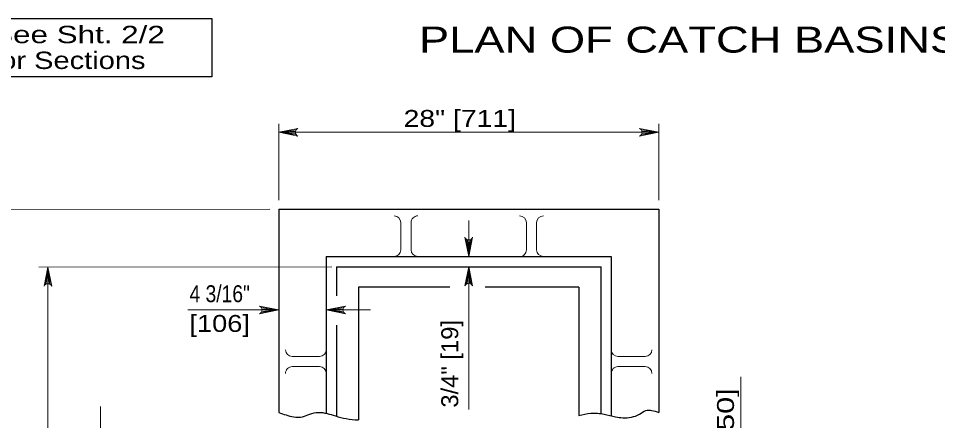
# Model space of a CAD drawing. Extents: x 1083.1 to 1117.1, y 719.4 to 763.4.
# Drawn here: x 1087.41 to 1095.88, y 747.79 to 751.5 of the extents above; entities that cross this region are included whole.
import ezdxf
from ezdxf.enums import TextEntityAlignment as Align

# ---------------------------------------------------------------- set-up
doc = ezdxf.new("R2010")
doc.units = 0
doc.header["$LTSCALE"] = 0.062
doc.layers.add('1', color=7, linetype='Continuous', lineweight=13)

msp = doc.modelspace()

# ---------------------------------------------------------------- linework, layer by layer
at = {"layer": '1'}
for p, q in [((1089.807, 749.82683), (1089.807, 750.53)), ((1089.96733, 750.47425), (1089.807, 750.45183)), ((1093.1465, 750.47425), (1093.30683, 750.45183)), ((1093.30683, 749.82683), (1093.30683, 750.53)), ((1089.96192, 750.46317), (1089.807, 750.45183)), ((1091.83508, 750.45183), (1089.807, 750.45183)), ((1089.96025, 750.45183), (1089.807, 750.45183)), ((1089.96308, 750.43742), (1089.807, 750.45183)), ((1089.96917, 750.42708), (1089.807, 750.45183)), ((1091.83508, 750.45183), (1093.30683, 750.45183)), ((1093.14467, 750.42708), (1093.30683, 750.45183)), ((1093.15075, 750.43742), (1093.30683, 750.45183)), ((1093.15192, 750.46317), (1093.30683, 750.45183)), ((1093.15358, 750.45183), (1093.30683, 750.45183)), ((1087.12858, 749.74008), (1089.72367, 749.74367)), ((1091.55692, 749.63942), (1091.55692, 749.30608)), ((1090.93192, 749.36858), (1090.93192, 749.61858)), ((1091.02567, 749.36858), (1091.02567, 749.61858)), ((1092.08817, 749.36858), (1092.08817, 749.61858)), ((1092.18192, 749.36858), (1092.18192, 749.61858)), ((1091.5345, 749.46642), (1091.55692, 749.30608)), ((1091.54558, 749.461), (1091.55692, 749.30608)), ((1091.58167, 749.46833), (1091.55692, 749.30608)), ((1091.57133, 749.46217), (1091.55692, 749.30608)), ((1091.55692, 749.45933), (1091.55692, 749.30608)), ((1087.59733, 749.20892), (1090.29658, 749.21242)), ((1087.65583, 749.04675), (1087.68067, 749.20892)), ((1087.66625, 749.05283), (1087.68067, 749.20892)), ((1087.68067, 749.20892), (1087.68067, 747.79433)), ((1087.68067, 749.05567), (1087.68067, 749.20892)), ((1087.692, 749.05408), (1087.68067, 749.20892)), ((1087.70308, 749.04858), (1087.68067, 749.20892)), ((1091.53208, 749.05017), (1091.55692, 749.21242)), ((1091.5425, 749.05633), (1091.55692, 749.21242)), ((1091.55692, 749.21242), (1091.55692, 747.89417)), ((1091.55692, 749.05917), (1091.55692, 749.21242)), ((1091.56825, 749.0575), (1091.55692, 749.21242)), ((1091.57933, 749.05208), (1091.55692, 749.21242)), ((1089.807, 748.81325), (1088.96883, 748.81325)), ((1089.64483, 748.7885), (1089.807, 748.81325)), ((1089.64667, 748.83567), (1089.807, 748.81325)), ((1089.65092, 748.79883), (1089.807, 748.81325)), ((1089.65208, 748.82458), (1089.807, 748.81325)), ((1089.65375, 748.81325), (1089.807, 748.81325)), ((1090.40475, 748.83567), (1090.2445, 748.81325)), ((1090.39933, 748.82458), (1090.2445, 748.81325)), ((1090.65317, 748.81325), (1090.2445, 748.81325)), ((1090.39767, 748.81325), (1090.2445, 748.81325)), ((1090.4005, 748.79883), (1090.2445, 748.81325)), ((1090.40667, 748.7885), (1090.2445, 748.81325)), ((1090.182, 748.38433), (1089.932, 748.38433)), ((1092.93183, 748.38433), (1093.18183, 748.38433)), ((1090.182, 748.29058), (1089.932, 748.29058)), ((1092.93183, 748.29058), (1093.18183, 748.29058)), ((1094.06467, 748.19533), (1094.06467, 746.99992)), ((1088.16492, 747.92333), (1088.16492, 746.59367)), ((1087.68067, 744.21283), (1087.68067, 747.79433))]:
    msp.add_line(p, q, dxfattribs=at)
at = {"layer": '1', "lineweight": 25}
for p, q in [((1089.807, 749.74358), (1089.807, 747.86883)), ((1089.807, 749.74358), (1093.30683, 749.74358)), ((1093.30683, 749.74358), (1093.30683, 747.86883)), ((1090.2445, 749.30608), (1092.86933, 749.30608)), ((1090.2445, 749.30608), (1090.2445, 747.856)), ((1092.86933, 749.30608), (1092.86933, 747.83725)), ((1090.33825, 749.21242), (1092.77558, 749.21242)), ((1090.33825, 749.21242), (1090.33825, 748.94483)), ((1092.77558, 747.85667), (1092.77558, 749.21242)), ((1090.54142, 749.02492), (1090.54142, 747.8)), ((1091.38192, 749.02492), (1090.54142, 749.02492)), ((1092.57242, 749.02492), (1091.70892, 749.02492)), ((1092.57242, 749.02492), (1092.57242, 747.84083)), ((1090.33825, 748.67375), (1090.33825, 747.83383))]:
    msp.add_line(p, q, dxfattribs=at)
msp.add_lwpolyline([(1086.99083, 751.50217), (1089.19067, 751.50217), (1089.19067, 750.96433), (1086.99083, 750.96433)], close=True, dxfattribs=at)
at = {"layer": '1'}
for points in [[(1089.98408, 750.41642), (1089.807, 750.45183), (1089.98408, 750.48725)], [(1093.12975, 750.41642), (1093.30683, 750.45183), (1093.12975, 750.48725)], [(1091.59233, 749.48317), (1091.55692, 749.30608), (1091.5215, 749.48317)], [(1087.64525, 749.03183), (1087.68067, 749.20892), (1087.71608, 749.03183)], [(1091.5215, 749.03533), (1091.55692, 749.21242), (1091.59233, 749.03533)], [(1089.62992, 748.77783), (1089.807, 748.81325), (1089.62992, 748.84867)], [(1090.42158, 748.77783), (1090.2445, 748.81325), (1090.42158, 748.84867)]]:
    msp.add_lwpolyline(points, dxfattribs=at)
for centre, start, end in [((1089.99837, 750.45188), 112.08782, 247.91395), ((1093.11545, 750.45188), 292.08605, 67.91218), ((1091.55687, 749.49749), 202.08782, 337.91395), ((1087.6807, 749.01757), 22.08782, 157.91395), ((1091.55695, 749.021), 22.08782, 157.91395), ((1089.61562, 748.81331), 292.08605, 67.91218), ((1090.43585, 748.81331), 112.08782, 247.91395)]:
    msp.add_arc(centre, 0.03822, start, end, dxfattribs=at)
for centre, major_axis, start_param, end_param in [((1090.86944, 749.61856), (0.0625, 0), 6.2831853, 7.8539816), ((1091.08818, 749.61856), (0.0625, 0), 1.5707963, 3.1415927), ((1092.02564, 749.61856), (0.0625, 0), 6.2831853, 7.8539816), ((1092.24438, 749.61856), (-0.0625, 0), 4.712389, 6.2831853), ((1090.86944, 749.3686), (0.0625, 0), 4.712389, 6.2831853), ((1091.08818, 749.3686), (-0.0625, 0), 6.2831853, 7.8539816), ((1092.02564, 749.3686), (-0.0625, 0), 1.5707963, 3.1415927), ((1092.24438, 749.3686), (-0.0625, 0), 6.2831853, 7.8539816), ((1089.93199, 748.44682), (-0.0625, 0), 6.2831853, 7.8539816), ((1090.18197, 748.44682), (0.0625, 0), 4.712389, 6.2831853), ((1092.93185, 748.44682), (-0.0625, 0), 6.2831853, 7.8539816), ((1093.18183, 748.44682), (0.0625, 0), 4.712389, 6.2831853), ((1089.93199, 748.22811), (0.0625, 0), 1.5707963, 3.1415927), ((1090.18197, 748.22811), (0.0625, 0), 6.2831853, 7.8539816), ((1092.93185, 748.22811), (0.0625, 0), 1.5707963, 3.1415927), ((1093.18183, 748.22811), (0.0625, 0), 6.2831853, 7.8539816)]:
    msp.add_ellipse(centre, major_axis=major_axis, ratio=0.999895, start_param=start_param, end_param=end_param, dxfattribs=at)
at = {"layer": '1', "lineweight": 25}
for points in [[(1089.807, 747.86883), (1089.94517, 747.828), (1090.02683, 747.828), (1090.09217, 747.8525), (1090.17383, 747.86892), (1090.329, 747.83617), (1090.427, 747.81167), (1090.54142, 747.7995)], [(1092.57242, 747.84092), (1092.68108, 747.86075), (1092.80358, 747.8525), (1092.90983, 747.828), (1092.97517, 747.81983), (1093.13033, 747.8525), (1093.1875, 747.88525), (1093.30683, 747.86883)]]:
    msp.add_spline(points, degree=3, dxfattribs=at)

# ---------------------------------------------------------------- texts
at = {"layer": '1'}
for s, height, width, p in [('See Sht. 2/2', 0.16, 1.35, (1087.16783, 751.27333)), ('PLAN OF CATCH BASINS AND PAVEMENT JOINTS', 0.24, 1.3, (1091.09858, 751.18608)), ('for Sections', 0.16, 1.25, (1087.16783, 751.03533)), ('28" [711]', 0.156, 1.25, (1090.95717, 750.50133))]:
    msp.add_text(s, height=height, dxfattribs=dict(at, width=width)).set_placement(p)
for s, width, p in [('4 3/16"', 0.85, (1089.26325, 748.88517)), ('[106]', 1.2, (1089.26325, 748.61108))]:
    msp.add_text(s, height=0.156, dxfattribs=dict(at, width=width)).set_placement(p, align=Align.CENTER)
for s, width, p in [('3/4" [19]', 1.05, (1091.46017, 747.91267)), ('2" [50]', 1.35, (1094.00017, 747.28592))]:
    msp.add_text(s, height=0.156, rotation=90, dxfattribs=dict(at, width=width)).set_placement(p)

doc.saveas('drawing.dxf')
